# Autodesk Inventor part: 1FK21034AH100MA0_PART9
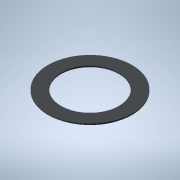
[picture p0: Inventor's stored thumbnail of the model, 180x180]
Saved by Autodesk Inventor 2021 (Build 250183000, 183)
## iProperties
Created: 2025-04
Part Number: 1FK21034AH100MA0_PART9
Material: Generic
Catalog Web Link: www.3dfindit.com
Description: -Servo synchronous motor
Document SubType Name: Modeling
Designer: psAdmin
Mass: 0.211555 g
Surface Area: 9.31012 cm^2
Volume: 0.211555 cm^3
Density: 1 g/cm^3
Appearance: PSOLRGB-212-217-219
Category: PARTsolutions
Title: 1FK21034AH100MA0_PART9
Author: Cadenas PARTsolutions
Comments: Servo synchronous motor
Sending System: PARTsolutions
Preprocessor: ST-DEVELOPER v19.3
PSOL_IDENT_0: {$CADENAS_DATA/23d-libs/siemens_ag/_cat_/39/97/1fk21034ah100ma0.prj},213 {VTYP=3D},{NB=1FK21034AH100
PSOL_IDENT_1: MA0_PART9},{LINA=1FK21034AH100MA0_PART9},{NN=1FK21034AH100MA0_PART9},{NOPRJ=TRUE},{DATE=19.08.2025 1
PSOL_IDENT_2: 4:00:33},{GEOMDATE=30.07.2025 02:02:21},{VERSION=},{LINEID=10},{WBVAR=},{WBNUMERIC=}  {NB=1FK21034AH
PSOL_IDENT_3: 100MA0_PART9},{LINA=1FK21034AH100MA0_PART9},{KT=DUMMY},{PREVIEW=../../../_pool_/d3/78/p_d211_xx_0093
PSOL_IDENT_4: 4j.png},{DESCSHORT=SIMOTICS S-1FK2 HD, SINAMICS S210 3AC 400V-480V, 1.01 Nm, 4500 rpm},{DESCLONG=SIM
PSOL_IDENT_5: OTICS S-1FK2 HD servo motor M0=1.27 Nm; PN = 0.48 kW at nN=4500 rpm (380-480 V); PN = 0.3 kW at nN=2
PSOL_IDENT_6: 500 rpm (200-240 V); with holding brake; degree of protection IP64; cylindrical shaft D14 x 30 mm; a
PSOL_IDENT_7: bsolute encoder 22-bit + 12-bit multiturn (encoder AM22DQC); with OCC interface; plug size M17, rota
PSOL_IDENT_8: table; SIMOTICS S-1FK2 servomotorfor a wide range of uses in industrial environments. SIMOTICS S‑1FK
PSOL_IDENT_9: 2 servomotors are compact synchronous motors with a high dynamic performance that set themselves apa
PSOL_IDENT_10: rt as a result of their high power density, degree of protection and overload capability. The motors
PSOL_IDENT_11: are available in two variants: as High Dynamic variant (highest dynamic performance as a result of
PSOL_IDENT_12: the low intrinsic moment of inertia for applications demanding a high dynamic performance with low m
PSOL_IDENT_13: oved masses) - and as Compact variant (precise and stable closed-loop control for medium up to large
PSOL_IDENT_14: moved masses as a result of a medium intrinsic moment of inertia). SIMOTICSS‑1FK2 servomotors fully
PSOL_IDENT_15: exploit their strengths in a system with the SINAMICSS210 frequency converter and simple connection
PSOL_IDENT_16: using the one cable connection (OCC). Advantages include the short control and positioning times, f
PSOL_IDENT_17: ast and precise correction of disturbing quantities as well as stable control with a high dynamic pe
PSOL_IDENT_18: rformance. The servo motors can be configured to address a wide range of requirements. For example w
PSOL_IDENT_19: ith and without holding brake, IP64 or IP65 degree of protection, singleturn or multiturn absolute e
PSOL_IDENT_20: ncoders - to name just a few. Further, the servomotors are available in different shaft heights exte
PSOL_IDENT_21: nding from 20 to 100. A shaft sealing ring is available to achieve an IP65 degree of protection and
PSOL_IDENT_22: for subsequent mounting at the motor or as spare part. SIMOTICS - the optimum motor for each and eve
PSOL_IDENT_23: ry motion control application.},{INTNO=195125454019},{SUPPLIERALTNO=1FK2103-4AH10-0MA0},{MANUID=1FK2
PSOL_IDENT_24: 1034AH100MA0},{MANUNAME=Siemens},{MANUTYPEDESC=SYNCHRONOUS MOTOR 1FK2 HD 1,27 NM},{AAU732=SIMOTICS},
PSOL_IDENT_25: {AAO057=S-1FK2},{AAU734=SIMOTICS S-1FK2 HD servo motor M0=1.27 Nm; PN = 0.48 kW at nN=4500 rpm (380-
PSOL_IDENT_26: 480 V); PN = 0.3 kW at nN=2500 rpm (200-240 V); with holding brake; degree of protection IP64; cylin
PSOL_IDENT_27: drical shaft D14 x 30 mm; absolute encoder 22-bit + 12-bit multiturn (encoder AM22DQC); with OCC int
PSOL_IDENT_28: erface; plug size M17, rotatable;},{AAW338=SYNCHRONOUS MOTOR 1FK2 HD 1,27 NM},{AAO742=SIMOTICS},{AAO
PSOL_IDENT_29: 663=4034106444921},{NOCUPEROU=1},{PRICEQUANTITY=1},{QUANTITYMIN=1},{QUANTITYINT=1},{CTN=85015100},{C
PSOL_IDENT_30: OO=RO},{AAO676=1FK2103-4AH10-0MA0},{AAO677=Siemens AG},{ORDERUNIT=C62},{CONTENTUNIT=C62}
NB: 1FK21034AH100MA0_PART9
NT: Servo synchronous motor
NBSYN: $MANUID._PART9
LINA: 1FK21034AH100MA0_PART9
CATALOG: SIEMENS
PREVIEW: ../../../_pool_/d3/78/p_d211_xx_00934j.png
DESCSHORT: SIMOTICS S-1FK2 HD, SINAMICS S210 3AC 400V-480V, 1.01 Nm, 4500 rpm
DESCLONG: SIMOTICS S-1FK2 HD servo motor M0=1.27 Nm; PN = 0.48 kW at nN=4500 rpm (380-480 V); PN = 0.3 kW at nN=2500 rpm (200-240 V); with holding brake; degree of protec
INTNO: 195125454019
SUPPLIERALTNO: 1FK2103-4AH10-0MA0
MANUID: 1FK21034AH100MA0
MANUNAME: Siemens
MANUTYPEDESC: SYNCHRONOUS MOTOR 1FK2 HD 1,27 NM
AAU732: SIMOTICS
AAO057: S-1FK2
AAU734: SIMOTICS S-1FK2 HD servo motor M0=1.27 Nm; PN = 0.48 kW at nN=4500 rpm (380-480 V); PN = 0.3 kW at nN=2500 rpm (200-240 V); with holding brake; degree of protec
AAW338: SYNCHRONOUS MOTOR 1FK2 HD 1,27 NM
AAO742: SIMOTICS
AAO663: 4034106444921.0
NOCUPEROU: 1
PRICEQUANTITY: 1
QUANTITYMIN: 1
QUANTITYINT: 1
CTN: 85015100
COO: RO
ARTICLENO: 1FK21034AH100MA0_PART9
BOMINFO: 1FK21034AH100MA0_PART9
CREATOR: CADENAS GmbH
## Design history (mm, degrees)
feature "2025_04_17_15_09_00_0361"
body "Solid1"
